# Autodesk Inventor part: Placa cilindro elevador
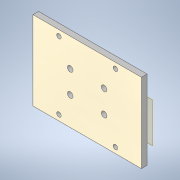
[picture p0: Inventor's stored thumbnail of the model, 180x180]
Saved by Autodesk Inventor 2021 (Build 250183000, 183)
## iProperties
Created: 2021-02
Part Number: Placa cilindro elevador
Material: Genérico
Document SubType Name: Modeling
Designer: ATOUZA
Density: 1 g/cm^3
Appearance: Valor por defecto
Author: ATOUZA
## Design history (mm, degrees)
node "Plano de trabajo1"
sketch "Boceto1"
  geometry: L1 (-48, -16)-(-48, 16) reference; L2 (48, -16)-(-48, -16) reference; L3 (48, 16)-(48, -16) reference; L4 (-48, 16)-(48, 16) reference; L5 (0, 16)-(0, -16); L6 (48, -35)-(-48, -35); L7 (-48, -35)-(-48, 35); L8 (-48, 35)-(48, 35); L9 (48, 35)-(48, -35); L10 (48, -35)-(-48, 35); L11 (-48, -35)-(48, 35); L12 (-48, 0)-(0, 0); L13 (-25, 0)-(-25, 35); C1 r 2.5 at (15, 10) reference; C2 r 2.5 at (15, -10) reference; C3 r 2.5 at (-15, 10) reference; C4 r 2.5 at (-15, -10) reference; C5 r 5 at (25, 0) reference; C6 r 5 at (-25, 0) reference; C7 r 2.5 at (-15, 10); C8 r 2.5 at (15, 10); C9 r 2.5 at (15, -10); C10 r 2.5 at (-15, -10); C11 r 2 at (-25, 30); C12 r 2 at (-25, -30); C13 r 2 at (25, -30); C14 r 2 at (25, 30)
  constraints: 18 end point, 8 centre point, 5 midpoint, 4 coincident, 4 concentric, 3 perpendicular, 3 symmetric about line, 2 parallel, 2 point on line, 1 horizontal, 3 other
  dimensions: "d0" = 96 distance of L7.end L8.end; "d1" = 70 distance of L6.end L7.end; "d2" = 4 diameter of C11; "d3" = 5 distance from line of L8 C11.centre; "d6" = 23 distance from line of L7 C11.centre (derived)
extrude "Extrusión1" new body sketch "Boceto1" distance "d4" = 5; taper "d5" = 0 deg
fillet "Empalme1" dims "d7" = 4
node "Sólido1"
node "Referencia1"
